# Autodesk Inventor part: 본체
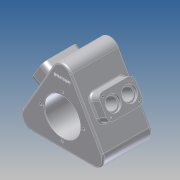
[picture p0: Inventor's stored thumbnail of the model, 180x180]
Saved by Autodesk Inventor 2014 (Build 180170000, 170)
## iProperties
Company: 한국ATC센터
Created: 2014-01
Part Number: 본체
Document SubType Name: Modeling
Designer: KYOUNG IL JANG
Density: 1 g/cm^3
Material: 알루미늄 6061
Mass: 657.987 g
Surface Area: 1165.97 cm^2
Volume: 657.987 cm^3
Vendor: CBT Solutions
Appearance: 알루미늄 - 평지
Author: KYOUNG IL JANG
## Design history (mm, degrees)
sketch "스케치1"
  geometry: C1 r 75 at (0, 0); C2 r 47.5 at (0, 0); 1 further point
  constraints: 2 centre point, 2 coincident
  dimensions: "d0" = 150 diameter of C1; "d1" = 95 diameter of C2
extrude "돌출1" new body sketch "스케치1" distance "d2" = 95; taper "d3" = 0 deg
node "작업 평면1"
  node "작업 평면3"
sketch "스케치2"
  geometry: L1 (95, 47.5)-(95, -47.5) reference; L2 (0, 47.5)-(0, -47.5) reference; L3 (0, -22.5)-(70, -22.5); L4 (70, -22.5)-(70, 22.5); L5 (70, 22.5)-(0, 22.5); 3 further points
  constraints: 6 end point, 3 perpendicular, 2 midpoint, 2 point on line, 1 horizontal alignment
  dimensions: "d5" = 45 distance of L3.end L4.end; "d104" = 70 distance of L4.end L5.end
extrude "돌출2" join sketch "스케치2" stored distance "d7" = 100; taper "d8" = 0 deg
fillet "모깎기1" dims "d9" = 10
sketch "스케치3"
  geometry: L1 (60.622, -55)-(-60.622, -55); L2 (-77.942, -25)-(-17.321, 80); L3 (17.321, 80)-(77.942, -25); A1 r 20 centre (-60.622, -35) between (-77.942, -25) and (-60.622, -55); A2 r 20 centre (0, 70) between (17.321, 80) and (-17.321, 80); A3 r 20 centre (60.622, -35) between (60.622, -55) and (77.942, -25); 5 further points
  constraints: 6 end point, 6 point on circle, 6 point on line, 6 tangent, 3 centre point, 2 equal radius, 1 coincident, 1 horizontal, 7 other
  dimensions: "d14" = 20 radius of A1; "d15" = 55 distance from line of L2 point (0, 0)
extrude "돌출3" join sketch "스케치3" distance "d16" = 15; taper "d17" = 0 deg
extrude "돌출9" join sketch "스케치3" distance "d100" = 80; taper "d101" = 0 deg
fillet "모깎기3" dims "d19" = 3
sketch "스케치4"
  geometry: C1 r 47.5 at (0, 0) reference; C2 r 32.5 at (0, 0); 1 further point
  constraints: 1 centre point, 1 coincident
  dimensions: "d20" = 65 diameter of C2
extrude "돌출4" cut sketch "스케치4" distance "d21" = 15; taper "d22" = 0 deg
fillet "모깎기4" dims "d23" = 3
sketch "스케치5"
  geometry: C1 r 35 at (0, 0); 1 further point
  constraints: 1 centre point, 1 coincident
  dimensions: "d25" = 70 diameter of C1
extrude "돌출5" cut sketch "스케치5" distance "d26" = 85; taper "d27" = 0 deg
sketch "스케치6"
  geometry: L1 (0, 12.5)-(0, -12.5) reference; 3 further points
  constraints: 2 horizontal alignment, 1 midpoint
  dimensions: "d108" = 20 distance from line of point (20, 0) L1; "d109" = 32 distance of point (52, 0) point (20, 0)
hole "구멍1" sketch "스케치6" at (20, 0), (52, 0) diameter "d30" = 22; stored, may be unused: countersink angle "d34" = 90 deg, drill point angle "d36" = 118 deg; dims "d31" = 6, "d32" = 28, "d33" = 5, "d35" = 8
node "작업 평면2"
sketch "스케치8"
  geometry: C1 r 18.5 at (0, 0); 1 further point
  constraints: 1 centre point, 1 coincident
  dimensions: "d44" = 37 diameter of C1
extrude "돌출7" cut sketch "스케치8" distance "d45" = 17; taper "d46" = 0 deg
sketch "스케치9"
  geometry: C1 r 13 at (0, 0); 1 further point
  constraints: 1 centre point, 1 coincident
  dimensions: "d47" = 26 diameter of C1
extrude "돌출8" cut sketch "스케치9" distance "d48" = 2; taper "d49" = 0 deg
fillet "모깎기6" dims "d50" = 3, "d51" = 0.3
chamfer "모따기1" distance "d52" = 1; stored, may be unused: second distance "d53" = 2, angle "d54" = 45 deg
sketch "스케치10"
  geometry: L1 (0, 12.5)-(0, -12.5) reference; A1 r 10 centre (60, -12.5) between (60, -22.5) and (70, -12.5) reference; 5 further points
  constraints: 2 horizontal alignment, 2 vertical alignment
  dimensions: "d58" = 7.5 distance from line of point (7.5, -16) L1; "d105" = 56 distance of point (7.5, -16) point (63.5, -16); "d106" = 32 distance of point (7.5, -16) point (7.5, 16); "d107" = 16 vertical distance of point (0, 0) point (7.5, -16) (= 0.5 x d106)
hole "구멍2" sketch "스케치10" at (7.5, -16), (63.5, -16), (63.5, 16), (7.5, 16) diameter "d59" = 3.242; stored, may be unused: countersink angle "d63" = 90 deg, drill point angle "d65" = 118 deg; dims "d60" = 10, "d61" = 4, "d62" = 2, "d64" = 13
sketch "스케치11" dims "d1" = 95
  geometry: C1 r 3.3 at (0, 42); C2 r 3.3 at (-34.641, -20) reference; C3 r 3.3 at (34.641, -20) reference; 1 further point
  constraints: 1 centre point, 1 vertical alignment
  dimensions: "d96" = 42 distance of point (0, 0) C1.centre
hole "구멍3" sketch "스케치11" at (0, 42) diameter "d72" = 5.242; stored, may be unused: countersink angle "d76" = 90 deg, drill point angle "d78" = 118 deg; dims "d73" = 12, "d74" = 4, "d75" = 2, "d77" = 15
chamfer "모따기2" distance "d93" = 1; stored, may be unused: second distance "d94" = 2, angle "d95" = 45 deg
sketch "스케치14"
  geometry: C1 r 36 at (0, 0) reference; 1 further point
  constraints: 1 vertical alignment, 1 other
  dimensions: "d110" = 65 distance of C1.centre point (0, 65)
feature "엠보싱2" sketch "스케치14" dims "d0" = 150, "d1" = 95, "d14" = 20, "d15" = 55, "d98" = 0.5, "d99" = 0
node "솔리드1"
pattern_circular "원형 패턴1" dims angle "d11" = 120 deg
pattern_circular "원형 패턴4" dims angle "d70" = 120 deg
pattern_circular "원형 패턴3" dims angle "d67" = 360 deg
pattern_circular "원형 패턴5" dims angle "d80" = 360 deg
node "투영된 루프1"
node "투영된 루프2"
node "참조2"
node "참조3"
other parameters: "d102" = 120 deg, "d103" = -75
